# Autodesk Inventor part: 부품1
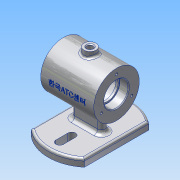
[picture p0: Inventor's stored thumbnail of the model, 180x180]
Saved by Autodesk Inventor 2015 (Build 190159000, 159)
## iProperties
Created: 2017-12
Part Number: 부품1
Material: 알루미늄 6061
Document SubType Name: Modeling
Designer: Administrator
Density: 2.7 g/cm^3
Appearance: 알루미늄 - 평지
Mass: 465.996 g
Surface Area: 486.574 cm^2
Volume: 172.591 cm^3
Author: Administrator
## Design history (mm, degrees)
sketch "스케치1"
  geometry: C1 r 55 at (0, 0); 1 further point
  constraints: 1 centre point, 1 coincident
  dimensions: "d0" = 110 diameter of C1
extrude "돌출1" new body sketch "스케치1" distance "d1" = 10; taper "d2" = 0 deg
node "작업 평면1"
sketch "스케치2"
  geometry: L1 (55, 10)-(-55, 10) reference; L2 (-55, 0)-(55, 0) reference; L3 (-55, 0)-(55, 0); L4 (55, 0)-(55, 10); L5 (55, 10)-(-55, 10); L6 (-55, 10)-(-55, 0); 1 further point
  constraints: 8 end point, 2 parallel, 1 horizontal, 1 perpendicular
extrude "돌출2" cut sketch "스케치2" distance "d4" = 20; taper "d5" = 0 deg; dims "d10" = 62
node "작업 평면2"
sketch "스케치3"
  geometry: L1 (42.426, 10)-(42.426, 0) reference; L2 (-42.426, 0)-(42.426, 0) reference; L3 (-42.426, 0)-(-42.426, 10) reference; L4 (42.426, 10)-(-42.426, 10) reference; L5 (-42.426, 0)-(42.426, 0); L6 (42.426, 0)-(42.426, 10); L7 (42.426, 10)-(-42.426, 10); L8 (-42.426, 10)-(-42.426, 0); 1 further point
  constraints: 8 end point, 2 parallel, 1 horizontal, 1 perpendicular
extrude "돌출3" cut sketch "스케치3" distance "d8" = 20; taper "d9" = 0 deg
sketch "스케치4"
  geometry: L1 (35, 10)-(35, 0) reference; L2 (-35, 0)-(35, 0) reference; L3 (-35, 0)-(-35, 10) reference; L4 (35, 10)-(-35, 10) reference; L5 (-35, 62)-(35, 62); L6 (-35, 62)-(-35, 92); L7 (-35, 92)-(35, 92); L8 (35, 92)-(35, 62); 1 further point
  constraints: 8 end point, 2 perpendicular, 1 horizontal, 1 vertical
  dimensions: "d10" = 62 distance between parallel lines of L2 L5; "d11" = 70 distance of L5.start L5.end; "d12" = 60 diameter of L7 L5; "d13" = 62 distance of L2.start L5.start
revolve "회전1" sketch "스케치4" stored, may be unused: angle "d14" = 90 deg
sketch "스케치10"
  geometry: L1 (-35, 92)-(35, 92) reference; L2 (-35, 32)-(-35, 92) reference; 2 further points
  constraints: 1 other
  dimensions: "d66" = 35 distance from line of point (0, 62) L2; "d67" = 30 distance from line of point (0, 62) L1
feature "엠보싱1" sketch "스케치10" dims "d68" = 0.5, "d69" = 0
sketch "스케치5"
  geometry: L1 (15, -5)-(-15, -5); L2 (-15, 5)-(15, 5); A1 r 5 centre (-15, 0) between (-15, 5) and (-15, -5); A2 r 5 centre (15, 0) between (15, -5) and (15, 5); 1 further point
  constraints: 4 end point, 4 point on circle, 4 tangent, 2 centre point, 2 horizontal, 1 horizontal alignment
  dimensions: "d15" = 30 distance of A1.centre A2.centre; "d16" = 15 distance of A2.centre point (0, 0); "d17" = 5 radius of A1
extrude "돌출4" join sketch "스케치5" distance "d18" = 62; taper "d19" = 0 deg
node "작업 평면4"
sketch "스케치6"
  geometry: L1 (-35, 30)-(-35, -30) reference; C1 r 8 at (0, 0); 1 further point
  constraints: 1 centre point, 1 coincident
  dimensions: "d22" = 16 diameter of C1
extrude "돌출5" join sketch "스케치6" distance "d23" = 25; taper "d24" = 0 deg
sketch "스케치7"
  geometry: L1 (-35, 92)-(35, 92) reference; L2 (-35, 32)-(-35, 92) reference; L3 (-35, 32)-(35, 32) reference; L4 (35, 32)-(35, 92) reference; L5 (-35, 62)-(35, 62); L6 (-35, 0)-(35, 0) reference; L7 (-35, 78)-(-23.3, 78); L8 (-23, 77.7)-(-23, 76); L9 (-23, 76)-(-20, 76); L10 (-20, 76)-(-20, 84); L11 (-17, 87)-(17, 87); L12 (20, 84)-(20, 76); L13 (20, 76)-(23, 76); L14 (23, 76)-(23, 77.7); L15 (23.3, 78)-(35, 78); L16 (-35, 78)-(-35, 62); L17 (35, 78)-(35, 62); A1 r 0.3 centre (-23.3, 77.7) between (-23, 77.7) and (-23.3, 78); A2 r 0.3 centre (23.3, 77.7) between (23.3, 78) and (23, 77.7); A3 r 3 centre (-17, 84) between (-17, 87) and (-20, 84); A4 r 3 centre (17, 84) between (20, 84) and (17, 87); 5 further points
  constraints: 24 end point, 12 point on line, 8 point on circle, 8 tangent, 7 perpendicular, 4 centre point, 2 equal radius, 2 midpoint, 1 collinear, 1 horizontal, 1 vertical
  dimensions: "d25" = 12 distance of L7.start point (-23, 78); "d26" = 12 distance of point (23, 78) L15.end; "d27" = 40 distance of point (-20, 87) point (20, 87); "d28" = 3 distance of L8.end L9.end; "d29" = 32 diameter of L7 L5; "d30" = 28 diameter of L9 L5; "d31" = 50 diameter of L11 L5; "d32" = 28 diameter of L13 L5; "d33" = 0.3 radius of A1; "d34" = 3 radius of A3
revolve "회전2" sketch "스케치7" stored, may be unused: angle "d35" = 90 deg
hole "구멍1" diameter "d38" = 8; stored, may be unused: countersink angle "d42" = 90 deg, drill point angle "d44" = 0 deg; dims "d36" = 10, "d37" = 10, "d39" = 6, "d40" = 4, "d41" = 2, "d43" = 30
sketch "스케치9"
  geometry: L1 (-35, -42.426)-(-35, 42.426) reference; L2 (35, 42.426)-(35, -42.426) reference; L3 (5, -40)-(5, -24); L4 (-5, -24)-(-5, -40); L5 (5, 24)-(5, 40); L6 (-5, 40)-(-5, 24); A1 r 55 centre (0, 0) between (35, 42.426) and (-35, 42.426) reference; A2 r 55 centre (0, 0) between (-35, -42.426) and (35, -42.426) reference; A3 r 5 centre (0, -24) between (5, -24) and (-5, -24); A4 r 5 centre (0, -40) between (-5, -40) and (5, -40); A5 r 5 centre (0, 40) between (5, 40) and (-5, 40); A6 r 5 centre (0, 24) between (-5, 24) and (5, 24); 1 further point
  constraints: 8 end point, 8 point on circle, 8 tangent, 4 centre point, 3 vertical, 2 vertical alignment, 1 parallel
  dimensions: "d56" = 24 distance of A3.centre point (0, 0); "d57" = 16 distance of A4.centre A3.centre; "d58" = 5 radius of A4; "d59" = 24 distance of A6.centre point (0, 0); "d60" = 16 distance of A5.centre A6.centre; "d61" = 5 radius of A5
extrude "돌출6" cut sketch "스케치9" distance "d62" = 25; taper "d63" = 0 deg
fillet "모깎기1" dims "d64" = 5
fillet "모깎기2" dims "d65" = 3
fillet "모깎기3" dims "d70" = 3
chamfer "모따기1" distance "d71" = 1; stored, may be unused: second distance "d72" = 2, angle "d73" = 45 deg
chamfer "모따기2" distance "d74" = 1; stored, may be unused: second distance "d75" = 2, angle "d76" = 45 deg
chamfer "모따기3" distance "d77" = 1; stored, may be unused: second distance "d78" = 2, angle "d79" = 45 deg
sketch "스케치11" dims "d80" = 46
  geometry: C1 r 30 at (0, 0) reference; 3 further points
  constraints: 2 horizontal alignment, 1 coincident, 2 other
hole "구멍3" sketch "스케치11" at (23, 0) diameter "d81" = 3.242; stored, may be unused: countersink angle "d85" = 90 deg, drill point angle "d87" = 118 deg; dims "d82" = 8, "d83" = 4, "d84" = 2, "d86" = 10
node "솔리드1"
pattern_circular "원형 패턴2" dims angle "d89" = 360 deg
mirror "대칭2"
node "투영된 루프1"
node "투영된 루프2"
node "투영된 루프3"
node "투영된 루프4"
other parameters: "d3" = 35, "d20" = 99
